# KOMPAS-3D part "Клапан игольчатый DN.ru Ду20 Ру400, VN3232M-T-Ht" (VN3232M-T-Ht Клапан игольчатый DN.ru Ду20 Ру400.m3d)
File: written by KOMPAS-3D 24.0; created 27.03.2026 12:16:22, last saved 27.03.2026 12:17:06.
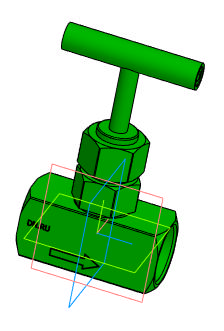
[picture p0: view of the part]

Document properties: Автор: Илья; Полное имя файла: D:\Обмен\Заказы с фриланса\DN.ru\VNxxM-T-Ht Клапан игольчатый DN.ru Ду8-50 Ру400\VN3232M-T-Ht Клапан игольчатый DN.ru Ду8-50 Ру400\DN20\VN3232M-T-Ht Клапан игольчатый DN.ru Ду20 Ру400.m3d

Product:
- Body: Body9  | qty 1
    Масса: 0.433192
- Part/product: Клапан игольчатый DN.ru Ду20 Ру400  | designation VN3232M-T-Ht
    Масса: 0.5
    Раздел спецификации: Прочие изделия
    Примечание: D090-02132

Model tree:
1. Body9  (labels: Body9)

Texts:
  VN3232M-T-Ht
